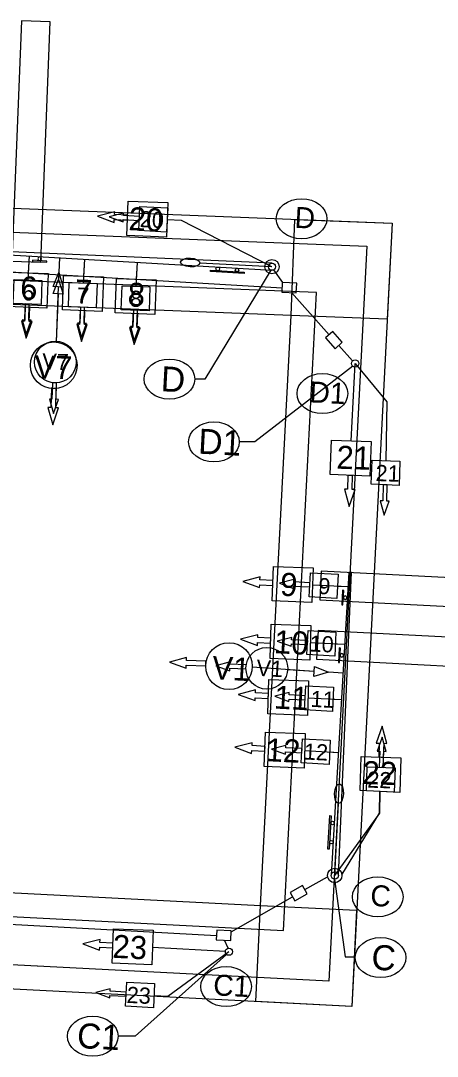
# Model space of a CAD drawing. Extents: x 21 to 686546, y 24 to 735466.
# Drawn here: x 680987.4 to 681074.1, y 735043.6 to 735258.8 of the extents above; entities that cross this region are included whole.
import ezdxf

# ---------------------------------------------------------------- set-up
doc = ezdxf.new("R2010")
doc.units = 0
for name, color, linetype in [('PEDXLIMITS-PR', 7, 'Continuous'), ('signal wiring diagram', 7, 'Continuous'), ('SIGNAL-PLAN VIEW LABLES', 7, 'Continuous'), ('SIGNAL-PR', 7, 'Continuous'), ('signal-pr-conduit', 7, 'Continuous'), ('Video-Zones-pr', 7, 'Continuous')]:
    doc.layers.add(name, color=color, linetype=linetype)

# ---------------------------------------------------------------- blocks, each defined once
blk = doc.blocks.new('STREET NAME SIGN')
at = {"layer": 'SIGNAL-PR'}
blk.add_lwpolyline([(1.5, 0.96), (1.49, 0.71), (-5.5, 0.9), (-5.5, 1.15)], close=True, dxfattribs=at)
for centre in [(-4, 0.49), (-0.01, 0.37)]:
    blk.add_circle(centre, 0.375, dxfattribs=at)
blk = doc.blocks.new('R10-12 SIGN')
at = {"layer": 'SIGNAL-PR'}
blk.add_lwpolyline([(1.52, 0.75), (-1.48, 0.75), (-1.48, 1), (1.52, 1), (1.52, 0.75)], close=True, dxfattribs=at)
blk.add_circle((0.02, 0.37), 0.375, dxfattribs=at)

msp = doc.modelspace()

# ---------------------------------------------------------------- linework, layer by layer
at = {"layer": 'PEDXLIMITS-PR'}
for points in [[(681056.26, 735053.96), (680884.52, 735062.77), (680892.76, 735223.49), (681064.67, 735216.71)], [(681051.53, 735059.21), (680889.77, 735067.5), (680897.5, 735218.3), (681059.42, 735211.91)], [(681043.65, 735197.52), (681044.44, 735217.5), (681064.67, 735216.71), (681063.64, 735196.73)], [(680906.98, 735207.92), (680900.27, 735076.98), (681042.06, 735069.71), (681048.91, 735202.32)], [(680911.72, 735202.73), (680905.52, 735081.72), (681037.32, 735074.96), (681043.65, 735197.52)], [(681037.32, 735074.96), (681057.29, 735073.93), (681056.26, 735053.96), (681036.3, 735054.99)]]:
    msp.add_lwpolyline(points, close=True, dxfattribs=at)
at = {"layer": 'signal wiring diagram'}
for p, q in [((681039.69, 735207.67), (681020.88, 735217.24)), ((681030.74, 735065.33), (681018.06, 735056.04)), ((681018.06, 735056.04), (681015.15, 735056.19))]:
    msp.add_line(p, q, dxfattribs=at)
for points in [[(681008.78, 735218.3), (681008.8, 735218.8), (681005.81, 735218.03), (681008.71, 735216.96), (681008.73, 735217.46), (681012.09, 735217.29), (681012.13, 735218.13), (681008.78, 735218.3)], [(681012.13, 735218.13), (681008.78, 735218.3), (681008.8, 735218.8), (681005.81, 735218.03), (681008.71, 735216.96), (681008.73, 735217.46), (681012.09, 735217.29)], [(681020.88, 735217.24), (681017.88, 735217.39)], [(680989.19, 735209.89), (680988.93, 735204.93)], [(680995.49, 735209.48), (680995.31, 735205)], [(681000.67, 735209.21), (681000.42, 735204.25)], [(681011.65, 735208.57), (681011.4, 735203.61)], [(680995.2, 735202.04), (680994.81, 735192.19)], [(680988.28, 735196.57), (680987.77, 735196.59), (680988.6, 735193.61), (680989.62, 735196.53), (680989.12, 735196.54), (680989.23, 735199.9), (680988.39, 735199.93), (680988.28, 735196.57)], [(680988.39, 735199.93), (680988.28, 735196.57), (680987.77, 735196.59), (680988.6, 735193.61), (680989.62, 735196.53), (680989.12, 735196.54), (680989.23, 735199.9)], [(680999.76, 735195.9), (680999.26, 735195.91), (681000.08, 735192.93), (681001.1, 735195.85), (681000.6, 735195.87), (681000.71, 735199.22), (680999.88, 735199.25), (680999.76, 735195.9)], [(680999.88, 735199.25), (680999.76, 735195.9), (680999.26, 735195.91), (681000.08, 735192.93), (681001.1, 735195.85), (681000.6, 735195.87), (681000.71, 735199.22)], [(681010.74, 735195.25), (681010.24, 735195.27), (681011.06, 735192.29), (681012.08, 735195.2), (681011.58, 735195.22), (681011.7, 735198.58), (681010.86, 735198.61), (681010.74, 735195.25)], [(681010.86, 735198.61), (681010.74, 735195.25), (681010.24, 735195.27), (681011.06, 735192.29), (681012.08, 735195.2), (681011.58, 735195.22), (681011.7, 735198.58)], [(681056.99, 735187.56), (681063.6, 735179.58), (681063.39, 735167.36)], [(680993.94, 735180.14), (680993.44, 735180.16), (680994.27, 735177.18), (680995.28, 735180.1), (680994.78, 735180.12), (680994.89, 735183.48), (680994.05, 735183.5), (680993.94, 735180.14)], [(680994.05, 735183.5), (680993.94, 735180.14), (680993.44, 735180.16), (680994.27, 735177.18), (680995.28, 735180.1), (680994.78, 735180.12), (680994.89, 735183.48)], [(680994.47, 735183.51), (680994.47, 735183.49)], [(681062.71, 735159), (681062.21, 735159.02), (681063.03, 735156.04), (681064.06, 735158.96), (681063.55, 735158.97), (681063.67, 735162.33), (681062.83, 735162.36), (681062.71, 735159)], [(681062.83, 735162.36), (681062.71, 735159), (681062.21, 735159.02), (681063.03, 735156.04), (681064.06, 735158.96), (681063.55, 735158.97), (681063.67, 735162.33)], [(681044.22, 735142.15), (681044.25, 735142.65), (681041.26, 735141.88), (681044.16, 735140.81), (681044.18, 735141.31), (681047.54, 735141.14), (681047.58, 735141.98), (681044.22, 735142.15)], [(681047.58, 735141.98), (681044.22, 735142.15), (681044.25, 735142.65), (681041.26, 735141.88), (681044.16, 735140.81), (681044.18, 735141.31), (681047.54, 735141.14)], [(681055.52, 735141.12), (681053.33, 735141.24)], [(681043.76, 735130.14), (681043.78, 735130.64), (681040.79, 735129.87), (681043.69, 735128.8), (681043.72, 735129.3), (681047.07, 735129.13), (681047.11, 735129.97), (681043.76, 735130.14)], [(681047.11, 735129.97), (681043.76, 735130.14), (681043.78, 735130.64), (681040.79, 735129.87), (681043.69, 735128.8), (681043.72, 735129.3), (681047.07, 735129.13)], [(681054.78, 735129.13), (681052.86, 735129.23)], [(681030.94, 735125.05), (681030.96, 735125.55), (681027.98, 735124.74), (681030.89, 735123.71), (681030.91, 735124.21), (681034.27, 735124.09), (681034.3, 735124.93), (681030.94, 735125.05)], [(681034.3, 735124.93), (681030.94, 735125.05), (681030.96, 735125.55), (681027.98, 735124.74), (681030.89, 735123.71), (681030.91, 735124.21), (681034.27, 735124.09)], [(681048.47, 735123.56), (681042.95, 735123.93)], [(681054.46, 735123.21), (681051.43, 735123.39)], [(681043.27, 735118.67), (681043.29, 735119.17), (681040.3, 735118.4), (681043.2, 735117.32), (681043.23, 735117.83), (681046.58, 735117.66), (681046.62, 735118.49), (681043.27, 735118.67)], [(681046.62, 735118.49), (681043.27, 735118.67), (681043.29, 735119.17), (681040.3, 735118.4), (681043.2, 735117.32), (681043.23, 735117.83), (681046.58, 735117.66)], [(681054.14, 735117.66), (681052.37, 735117.75)], [(681062.92, 735106.97), (681063.42, 735106.95), (681062.6, 735109.93), (681061.58, 735107.01), (681062.08, 735107), (681061.97, 735103.64), (681062.8, 735103.61), (681062.92, 735106.97)], [(681062.8, 735103.61), (681062.92, 735106.97), (681063.42, 735106.95), (681062.6, 735109.93), (681061.58, 735107.01), (681062.08, 735107), (681061.97, 735103.64)], [(681042.58, 735107.69), (681042.6, 735108.19), (681039.61, 735107.42), (681042.51, 735106.35), (681042.53, 735106.85), (681045.89, 735106.68), (681045.93, 735107.52), (681042.58, 735107.69)], [(681045.93, 735107.52), (681042.58, 735107.69), (681042.6, 735108.19), (681039.61, 735107.42), (681042.51, 735106.35), (681042.53, 735106.85), (681045.89, 735106.68)], [(681053.49, 735106.68), (681051.68, 735106.78)], [(681052.74, 735081.17), (681062.13, 735094.1), (681062.21, 735098.61)], [(681006.05, 735057.1), (681006.07, 735057.6), (681003.08, 735056.83), (681005.98, 735055.76), (681006, 735056.26), (681009.36, 735056.09), (681009.4, 735056.93), (681006.05, 735057.1)], [(681009.4, 735056.93), (681006.05, 735057.1), (681006.07, 735057.6), (681003.08, 735056.83), (681005.98, 735055.76), (681006, 735056.26), (681009.36, 735056.09)]]:
    msp.add_lwpolyline(points, dxfattribs=at)
for points in [[(681011.98, 735215.22), (681012.24, 735220.2), (681018.01, 735219.91), (681017.75, 735214.87)], [(680985.89, 735200.04), (680986.06, 735205.03), (680991.84, 735204.83), (680991.66, 735199.79)], [(680995.31, 735205), (680996.24, 735201.99), (680994.16, 735202.09)], [(680997.37, 735199.36), (680997.54, 735204.35), (681003.32, 735204.15), (681003.15, 735199.12)], [(681008.35, 735198.72), (681008.53, 735203.71), (681014.3, 735203.51), (681014.13, 735198.47)], [(681060.33, 735162.47), (681060.5, 735167.46), (681066.28, 735167.26), (681066.1, 735162.22)], [(681047.43, 735139.06), (681047.69, 735144.05), (681053.46, 735143.75), (681053.2, 735138.72)], [(681046.96, 735127.05), (681047.22, 735132.04), (681052.99, 735131.74), (681052.73, 735126.71)], [(681051.43, 735123.39), (681048.4, 735122.52), (681048.54, 735124.6)], [(681046.47, 735115.58), (681046.73, 735120.57), (681052.5, 735120.27), (681052.24, 735115.24)], [(681045.78, 735104.6), (681046.04, 735109.59), (681051.81, 735109.29), (681051.55, 735104.26)], [(681059.32, 735098.73), (681059.5, 735103.72), (681065.27, 735103.52), (681065.1, 735098.49)], [(681009.25, 735054.01), (681009.51, 735059), (681015.28, 735058.7), (681015.02, 735053.67)]]:
    msp.add_lwpolyline(points, close=True, dxfattribs=at)
for centre in [(680994.64, 735187.85), (681038.62, 735124.22)]:
    msp.add_circle(centre, 4.34, dxfattribs=at)
for centre in [(681045.84, 735217.63), (681050.16, 735181.3), (681061.69, 735076.73), (681030.15, 735058.09)]:
    msp.add_ellipse(centre, major_axis=(-5.27, 0), ratio=0.790685, dxfattribs=at)
at = {"layer": 'SIGNAL-PLAN VIEW LABLES'}
for p, q in [((681006.99, 735219.09), (681003.39, 735218.16)), ((681006.95, 735218.48), (681006.99, 735219.09)), ((681003.39, 735218.16), (681006.87, 735216.87)), ((681006.87, 735216.87), (681006.9, 735217.48)), ((681006.9, 735217.48), (681009.61, 735217.34)), ((681009.65, 735218.35), (681006.95, 735218.48)), ((681009.61, 735217.34), (681009.65, 735218.35)), ((681039.69, 735207.67), (681020.88, 735217.24)), ((680988.3, 735199.25), (680988.2, 735196.35)), ((680989.31, 735199.2), (680988.3, 735199.25)), ((680989.21, 735196.31), (680989.31, 735199.2)), ((680999.78, 735198.56), (680999.68, 735195.67)), ((681000.79, 735198.51), (680999.78, 735198.56)), ((681000.69, 735195.64), (681000.79, 735198.51)), ((681010.76, 735197.91), (681010.66, 735195.03)), ((681011.77, 735197.87), (681010.76, 735197.91)), ((681011.67, 735194.99), (681011.77, 735197.87)), ((680988.2, 735196.35), (680987.6, 735196.37)), ((680987.6, 735196.37), (680988.58, 735192.79)), ((680988.58, 735192.79), (680989.81, 735196.29)), ((680989.81, 735196.29), (680989.21, 735196.31)), ((680999.68, 735195.67), (680999.08, 735195.69)), ((680999.08, 735195.69), (681000.06, 735192.12)), ((681000.06, 735192.12), (681001.29, 735195.62)), ((681001.29, 735195.62), (681000.69, 735195.64)), ((681010.66, 735195.03), (681010.06, 735195.05)), ((681010.06, 735195.05), (681011.04, 735191.47)), ((681011.04, 735191.47), (681012.27, 735194.97)), ((681012.27, 735194.97), (681011.67, 735194.99)), ((681056.16, 735171.45), (681056.99, 735187.56)), ((681055.46, 735164.31), (681055.36, 735161.42)), ((681056.46, 735164.26), (681055.46, 735164.31)), ((681056.36, 735161.39), (681056.46, 735164.26)), ((681055.36, 735161.42), (681054.75, 735161.44)), ((681054.75, 735161.44), (681055.74, 735157.87)), ((681055.74, 735157.87), (681056.97, 735161.37)), ((681056.97, 735161.37), (681056.36, 735161.39)), ((681037.23, 735143.2), (681033.63, 735142.28)), ((681033.63, 735142.28), (681037.11, 735140.99)), ((681037.11, 735140.99), (681037.14, 735141.59)), ((681037.14, 735141.59), (681039.85, 735141.45)), ((681037.19, 735142.6), (681037.23, 735143.2)), ((681039.89, 735142.46), (681037.19, 735142.6)), ((681039.85, 735141.45), (681039.89, 735142.46)), ((681036.76, 735131.2), (681033.17, 735130.27)), ((681036.73, 735130.59), (681036.76, 735131.2)), ((681039.42, 735130.45), (681036.73, 735130.59)), ((681039.39, 735129.45), (681039.42, 735130.45)), ((681033.17, 735130.27), (681036.65, 735128.98)), ((681036.65, 735128.98), (681036.68, 735129.58)), ((681036.68, 735129.58), (681039.39, 735129.45)), ((681036.27, 735119.72), (681032.68, 735118.8)), ((681036.24, 735119.12), (681036.27, 735119.72)), ((681032.68, 735118.8), (681036.16, 735117.51)), ((681036.16, 735117.51), (681036.19, 735118.11)), ((681036.19, 735118.11), (681038.9, 735117.97)), ((681038.93, 735118.98), (681036.24, 735119.12)), ((681038.9, 735117.97), (681038.93, 735118.98)), ((681062.6, 735112.19), (681061.37, 735108.69)), ((681063.59, 735108.62), (681062.6, 735112.19)), ((681035.58, 735108.74), (681031.99, 735107.82)), ((681031.99, 735107.82), (681035.46, 735106.53)), ((681035.46, 735106.53), (681035.49, 735107.13)), ((681035.49, 735107.13), (681038.2, 735106.99)), ((681035.55, 735108.14), (681035.58, 735108.74)), ((681038.24, 735108), (681035.55, 735108.14)), ((681038.2, 735106.99), (681038.24, 735108)), ((681061.37, 735108.69), (681061.98, 735108.67)), ((681061.98, 735108.67), (681061.88, 735105.79)), ((681062.88, 735105.76), (681062.98, 735108.64)), ((681062.98, 735108.64), (681063.59, 735108.62)), ((681061.88, 735105.79), (681062.88, 735105.76)), ((681003.94, 735067.87), (681000.35, 735066.94)), ((681000.35, 735066.94), (681003.83, 735065.66)), ((681003.83, 735065.66), (681003.86, 735066.26)), ((681003.86, 735066.26), (681006.57, 735066.12)), ((681003.91, 735067.27), (681003.94, 735067.87)), ((681006.61, 735067.13), (681003.91, 735067.27)), ((681006.57, 735066.12), (681006.61, 735067.13)), ((681030, 735065.39), (681014.84, 735066.17))]:
    msp.add_line(p, q, dxfattribs=at)
for points in [[(681009.5, 735214.14), (681009.75, 735221.28), (681018, 735220.99), (681017.75, 735213.79)], [(680984.63, 735199.4), (680984.88, 735206.54), (680993.14, 735206.25), (680992.89, 735199.05)], [(680995.37, 735206.44), (680996.29, 735203.44), (680994.22, 735203.54)], [(680996.11, 735198.71), (680996.36, 735205.85), (681004.62, 735205.56), (681004.37, 735198.36)], [(681007.1, 735198.07), (681007.34, 735205.2), (681015.6, 735204.91), (681015.35, 735197.71)], [(681051.79, 735164.46), (681052.04, 735171.6), (681060.29, 735171.31), (681060.04, 735164.11)], [(681039.74, 735138.26), (681039.99, 735145.39), (681048.24, 735145.11), (681047.99, 735137.91)], [(681039.28, 735126.25), (681039.52, 735133.38), (681047.78, 735133.1), (681047.53, 735125.9)], [(681051.43, 735123.39), (681048.4, 735122.52), (681048.54, 735124.6)], [(681038.79, 735114.78), (681039.03, 735121.91), (681047.29, 735121.62), (681047.04, 735114.42)], [(681038.09, 735103.8), (681038.34, 735110.93), (681046.6, 735110.64), (681046.35, 735103.45)], [(681058.01, 735098.79), (681058.25, 735105.92), (681066.51, 735105.63), (681066.26, 735098.43)], [(681006.46, 735062.93), (681006.71, 735070.06), (681014.96, 735069.77), (681014.71, 735062.57)]]:
    msp.add_lwpolyline(points, close=True, dxfattribs=at)
for points in [[(681009.65, 735218.35), (681006.95, 735218.48), (681006.99, 735219.09), (681003.39, 735218.16), (681006.87, 735216.87), (681006.9, 735217.48), (681009.61, 735217.34)], [(681020.88, 735217.24), (681017.88, 735217.39)], [(680989.19, 735209.89), (680989.01, 735206.38)], [(680995.49, 735209.48), (680995.37, 735206.44)], [(681000.67, 735209.21), (681000.49, 735205.7)], [(681011.65, 735208.57), (681011.47, 735205.06)], [(681039.48, 735206.93), (681025.72, 735184.31), (681023.62, 735184.31)], [(680995.25, 735203.49), (680994.8, 735192)], [(680988.3, 735199.25), (680988.2, 735196.35), (680987.6, 735196.37), (680988.58, 735192.79), (680989.81, 735196.29), (680989.21, 735196.31), (680989.31, 735199.2)], [(680999.78, 735198.56), (680999.68, 735195.67), (680999.08, 735195.69), (681000.06, 735192.12), (681001.29, 735195.62), (681000.69, 735195.64), (681000.79, 735198.51)], [(681010.76, 735197.91), (681010.66, 735195.03), (681010.06, 735195.05), (681011.04, 735191.47), (681012.27, 735194.97), (681011.67, 735194.99), (681011.77, 735197.87)], [(681056.48, 735187.02), (681036.15, 735171.26), (681032.88, 735171.26)], [(680993.71, 735178.38), (680993.1, 735178.4), (680994.1, 735174.83), (680995.32, 735178.33), (680994.71, 735178.35), (680994.84, 735182.38), (680993.83, 735182.41), (680993.71, 735178.38)], [(680993.83, 735182.41), (680993.71, 735178.38), (680993.1, 735178.4), (680994.1, 735174.83), (680995.32, 735178.33), (680994.71, 735178.35), (680994.84, 735182.38)], [(681055.46, 735164.31), (681055.36, 735161.42), (681054.75, 735161.44), (681055.74, 735157.87), (681056.97, 735161.37), (681056.36, 735161.39), (681056.46, 735164.26)], [(681039.89, 735142.46), (681037.19, 735142.6), (681037.23, 735143.2), (681033.63, 735142.28), (681037.11, 735140.99), (681037.14, 735141.59), (681039.85, 735141.45)], [(681055.52, 735141.12), (681048.12, 735141.5)], [(681039.42, 735130.45), (681036.73, 735130.59), (681036.76, 735131.2), (681033.17, 735130.27), (681036.65, 735128.98), (681036.68, 735129.58), (681039.39, 735129.45)], [(681054.78, 735129.13), (681047.65, 735129.49)], [(681021.91, 735125.87), (681021.93, 735126.47), (681018.35, 735125.49), (681021.85, 735124.26), (681021.87, 735124.86), (681025.9, 735124.72), (681025.93, 735125.72), (681021.91, 735125.87)], [(681025.93, 735125.72), (681021.91, 735125.87), (681021.93, 735126.47), (681018.35, 735125.49), (681021.85, 735124.26), (681021.87, 735124.86), (681025.9, 735124.72)], [(681048.47, 735123.56), (681035.59, 735124.42)], [(681054.46, 735123.21), (681051.43, 735123.39)], [(681038.93, 735118.98), (681036.24, 735119.12), (681036.27, 735119.72), (681032.68, 735118.8), (681036.16, 735117.51), (681036.19, 735118.11), (681038.9, 735117.97)], [(681054.14, 735117.66), (681047.16, 735118.02)], [(681062.88, 735105.76), (681062.98, 735108.64), (681063.59, 735108.62), (681062.6, 735112.19), (681061.37, 735108.69), (681061.98, 735108.67), (681061.88, 735105.79)], [(681038.24, 735108), (681035.55, 735108.14), (681035.58, 735108.74), (681031.99, 735107.82), (681035.46, 735106.53), (681035.49, 735107.13), (681038.2, 735106.99)], [(681053.49, 735106.68), (681046.47, 735107.04)], [(681054.23, 735081.3), (681062.05, 735094.1), (681062.13, 735098.61)], [(681052.71, 735080.42), (681054.91, 735064.29), (681057.01, 735064.29)], [(681006.61, 735067.13), (681003.91, 735067.27), (681003.94, 735067.87), (681000.35, 735066.94), (681003.83, 735065.66), (681003.86, 735066.26), (681006.57, 735066.12)], [(681030.24, 735064.77), (681011.21, 735047.77), (681007.68, 735047.76)]]:
    msp.add_lwpolyline(points, dxfattribs=at)
for centre in [(680994.32, 735187.17), (681030.75, 735124.66)]:
    msp.add_circle(centre, 4.85, dxfattribs=at)
for centre in [(681018.36, 735184.31), (681027.62, 735171.26), (681062.27, 735064.11), (681002.41, 735047.76)]:
    msp.add_ellipse(centre, major_axis=(-5.27, 0), ratio=0.790685, dxfattribs=at)
at = {"layer": 'SIGNAL-PR'}
for p, q in [((681039.69, 735207.67), (681024.71, 735208.43)), ((681052.74, 735081.17), (681053.51, 735096.15))]:
    msp.add_line(p, q, dxfattribs=at)
for points in [[(681039.73, 735208.42), (680974.24, 735211.27), (680974.21, 735210.77), (681039.65, 735206.92)], [(681053.49, 735081.13), (681056.24, 735144.09), (681055.7, 735144.12), (681051.99, 735081.21)]]:
    msp.add_lwpolyline(points, dxfattribs=at)
for points in [[(681041.73, 735202.4), (681044.73, 735202.26), (681044.82, 735204.26), (681041.82, 735204.39)], [(681050.82, 735192.87), (681052.81, 735190.63), (681054.31, 735191.95), (681052.32, 735194.2)], [(681044.44, 735075.88), (681047.03, 735077.38), (681046.03, 735079.11), (681043.44, 735077.61)], [(681028.1, 735067.81), (681031.1, 735067.67), (681031.19, 735069.67), (681028.19, 735069.81)]]:
    msp.add_lwpolyline(points, close=True, dxfattribs=at)
for centre, radius in [((681039.69, 735207.67), 1.5), ((681039.69, 735207.67), 0.75), ((681056.99, 735187.56), 0.75), ((681052.74, 735081.17), 1.5), ((681052.74, 735081.17), 0.75), ((681030.74, 735065.33), 0.75)]:
    msp.add_circle(centre, radius, dxfattribs=at)
for centre, major_axis in [((681022.69, 735208.54), (2.02, -0.1)), ((681053.62, 735098.17), (-0.11, -2.02))]:
    msp.add_ellipse(centre, major_axis=major_axis, ratio=0.447722, dxfattribs=at)
at = {"layer": 'signal-pr-conduit'}
for points in [[(680927.53, 735209.98), (681041.77, 735203.28)], [(681041.97, 735204.39), (681040.09, 735207.04)], [(681051.58, 735193.54), (681043.73, 735202.3)], [(681056.43, 735188.11), (681053.58, 735191.3)], [(681046.55, 735078.22), (681051.26, 735080.91)], [(681031.18, 735069.48), (681043.94, 735076.74)], [(680917.96, 735074.75), (681028.14, 735068.71)], [(681030.55, 735066.05), (681029.84, 735067.73)]]:
    msp.add_lwpolyline(points, dxfattribs=at)
at = {"layer": 'Video-Zones-pr'}
for points in [[(680987.57, 735258.78), (680985.6, 735208.82), (680991.59, 735208.58), (680993.57, 735258.54)], [(681049.61, 735138.43), (681099.55, 735135.85), (681099.85, 735141.84), (681049.92, 735144.42)], [(681048.97, 735126.09), (681098.91, 735123.51), (681099.22, 735129.5), (681049.28, 735132.08)]]:
    msp.add_lwpolyline(points, close=True, dxfattribs=at)

# ---------------------------------------------------------------- block references
at = {"layer": 'SIGNAL-PR'}
for p, yscale, rotation in [((680991.41, 735209.68), -1, -3.386662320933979), ((681055.27, 735138.89), -1.0000000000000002, -93.35905195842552), ((681054.58, 735126.91), -1.0000000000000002, -93.35905195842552)]:
    msp.add_blockref('R10-12 SIGN', p, dxfattribs=dict(at, yscale=yscale, rotation=rotation))
for p, rotation in [((681028.42, 735207.58), 178.27327617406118), ((681052.63, 735092.07), 88.262425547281)]:
    msp.add_blockref('STREET NAME SIGN', p, dxfattribs=dict(at, rotation=rotation))

# ---------------------------------------------------------------- texts
at = {"layer": 'signal wiring diagram'}
for s, height, rotation, p in [('20', 3.36, 357.0414, (681012.14, 735215.91)), ('D', 4.37, 357.0414, (681044.32, 735215.76)), ('6', 3.36, 357.9965, (680987.71, 735200.68)), ('7', 3.36, 357.9965, (680999.11, 735200)), ('8', 3.36, 357.9965, (681010.09, 735199.36)), ('V7', 3.36, 358.1697, (680991.87, 735186.3)), ('D1', 4.368, 357.0414, (681047.4, 735179.49)), ('21', 3.36, 357.9965, (681061.19, 735163.14)), ('9', 3.36, 357.0414, (681049.26, 735139.67)), ('10', 3.36, 357.0414, (681047.44, 735127.73)), ('V1', 3.36, 356.9474, (681036.39, 735122.66)), ('11', 3.36, 357.0414, (681047.67, 735116.22)), ('12', 3.36, 357.0414, (681046.26, 735105.28)), ('22', 3.36, 357.9965, (681059.47, 735099.43)), ('C', 4.37, 357.0414, (681060.06, 735074.86)), ('C1', 4.368, 357.0414, (681027.39, 735056.28)), ('23', 3.36, 357.0414, (681009.41, 735054.71))]:
    msp.add_text(s, height=height, rotation=rotation, dxfattribs=at).set_placement(p)
at = {"layer": 'SIGNAL-PLAN VIEW LABLES'}
for s, height, rotation, p in [('20', 4.8, 357.0414, (681009.79, 735215.28)), ('6', 4.8, 357.9965, (680987.27, 735200.9)), ('7', 4.8, 357.9965, (680998.64, 735200.23)), ('8', 4.8, 357.9965, (681009.62, 735199.58)), ('V7', 4.8, 358.1697, (680990.21, 735184.49)), ('D', 5.2, 357.0414, (681016.49, 735181.8)), ('D1', 5.2, 357.0414, (681024.27, 735168.83)), ('21', 4.8, 357.9965, (681053.04, 735165.7)), ('9', 4.8, 357.0414, (681041.3, 735139.32)), ('10', 4.8, 357.0414, (681040.04, 735127.37)), ('V1', 4.8, 356.9474, (681027.16, 735121.97)), ('11', 4.8, 357.0414, (681040.04, 735115.86)), ('12', 4.8, 357.0414, (681038.32, 735104.93)), ('22', 4.8, 357.9965, (681058.43, 735100.18)), ('23', 4.8, 357.0414, (681006.45, 735064.08)), ('C', 5.2, 357.0414, (681060.28, 735061.61)), ('C1', 5.2, 357.0414, (680999.06, 735045.33))]:
    msp.add_text(s, height=height, rotation=rotation, dxfattribs=at).set_placement(p)

doc.saveas('drawing.dxf')
